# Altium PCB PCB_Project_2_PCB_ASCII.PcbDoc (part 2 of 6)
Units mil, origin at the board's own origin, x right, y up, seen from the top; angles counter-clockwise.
Board outline 3900 x 7800 mil, 6 copper layers (Top Layer, GND 1, Signal, Power, GND 2, Bottom Layer), stack 62.1 mil thick; 636 components, 334 nets, 1830 pads, 1401 vias.
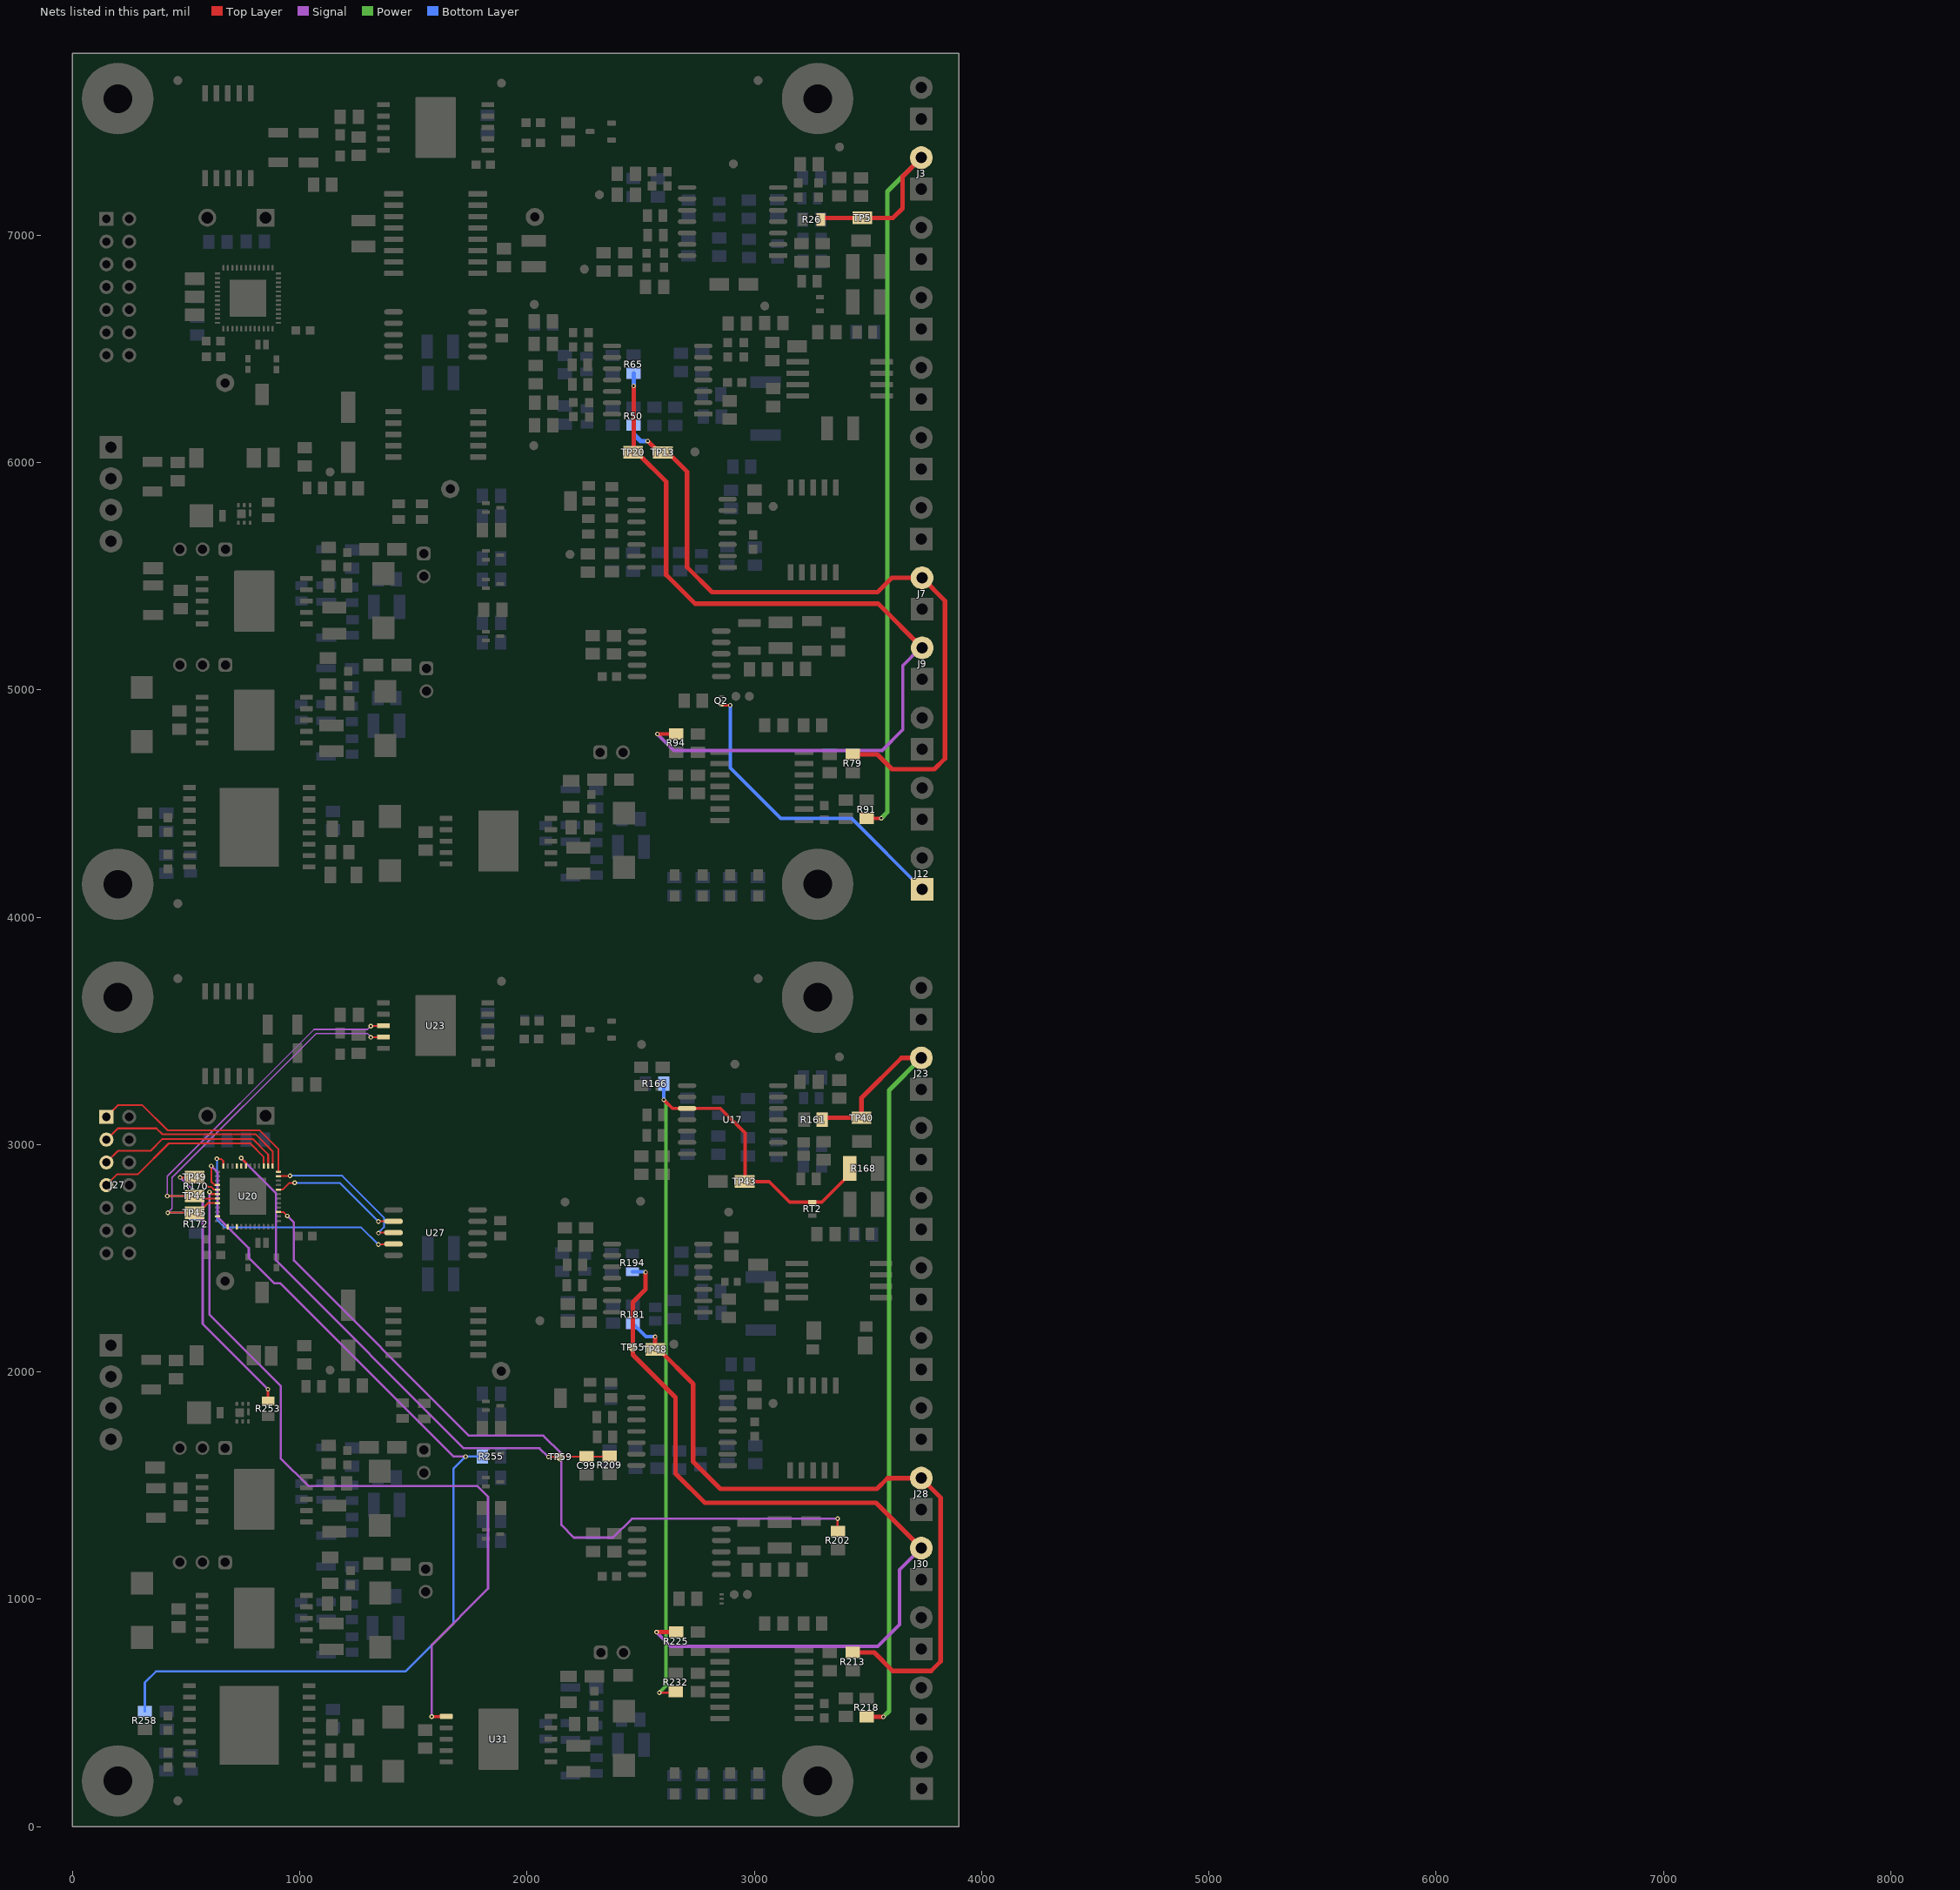
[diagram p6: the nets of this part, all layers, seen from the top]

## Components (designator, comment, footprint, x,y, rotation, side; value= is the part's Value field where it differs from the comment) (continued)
R212 "RT0805BRD0735K7L" 0805_HV 2574.22,1616.61 r90 bottom
R213 "ERJ-6ENF1372V" 0805_HV 3433,726 r90 top
R214 "ERJ-6ENF1502V" 0805_HV 3086,894 r180 top
R215 "CRCW080510K0FKEA" 0805_HV 3257.25,894 r180 top
R216 "ERJ-6ENF1001V" 0805_HV 3332.42,726 r270 top
R217 "ERJ-6GEYJ102V" 0805_HV 2894.38,184.79 r90 bottom
R218 "ERJ-6ENF1372V" 0805_HV 3495,524 r270 top
R219 "RR1220P-202-D" 0805_HV 3403,524.5 r90 top
R220 "ERJ-6GEYJ103V" 0805_HV 2938,2033 r180 bottom
R221 "ERJ-6GEYJ102V" 0805_HV 2879.81,1901.84 r270 bottom
R222 "RT0805BRD07626RL" 0805_HV 3000.72,1901.54 r90 top
R223 "ERJ-6GEYJ102V" 0805_HV 2773.24,184.79 r90 bottom
R224 "ERJ-6GEYJ104V" 0805_HV 3000.72,1901 r270 bottom
R225 "CRCW080510K7FKEA" 0805_HV 2656.04,815.81 r90 top
R226 "CRCW080514K7FKEA" 0805_HV 2751.35,816 r270 top
R227 "5106" 5106 2369.76,1919.81 r90 top
R228 "5106" 5106 2370,1909 r270 bottom
R229 "5106" 5106 2277.42,1920.55 r270 top
R230 "ERJ-6GEYJ102V" 0805_HV 2648.42,184.79 r90 bottom
R231 "5106" 5106 1882.44,2632 r270 top
R232 "ERJ-6ENF1102V" 0805_HV 2655.24,634.57 r270 top
R233 "CRCW080510K0FKEA" 0805_HV 2751.35,634.57 r90 top
R234 "5106" 5106 1453.1,1829.23 r90 top
R235 "5106" 5106 1549.06,1827.25 r90 top
R236 "RG2012P-102-B-T5" 0805_HV 1236.26,1939.42 r0 top
R237 "5106" 5106 1063.03,1937.05 r180 top
R238 "RC0603FR-0749R9L" 0603 1224.13,1094.55 r270 top
R239 "RC1206FR-073K9L" 1206 1134.69,1127.56 r90 top
R240 "5106" 5106 1007.16,950.73 r90 bottom
R241 "5106" 5106 1230.01,943.96 r90 bottom
R242 "5106" 5106 1231.36,801.72 r270 bottom
R243 "RG2012P-222-B-T5" 0805_HV 1230.01,1102.46 r90 bottom
R244 "RC0603FR-0749R9L" 0603 1209.85,1622.27 r270 top
R245 "ERJ-6GEYJ304V" 0805_HV 1844.04,1813 r180 bottom
R246 "RG2012P-4021-B-T5" 0805_HV 1127.05,1636.51 r90 top
R247 "ERJ-6ENF5761V" 0805_HV 1176.98,4286.01 r180 top
R248 "5106" 5106 1007.88,1473.9 r90 bottom
R249 "5106" 5106 1230.72,1467.12 r90 bottom
R250 "ERJ-6GEYJ302V" 0805_HV 1844.59,1752.65 r0 top
R251 "5106" 5106 1230.72,1327.76 r270 bottom
R252 "RT0805BRD076K42L" 0805_HV 320.45,4417.45 r270 top
R253 "5106" 5106 861.69,1838 r90 top
R254 "RT0805BRD07459RL" 0805_HV 1230.72,1625.62 r90 bottom
R255 "ERJ-6GEYJ203V" 0805_HV 1844.04,1627.66 r0 bottom
R256 "RN73C2A100KBTD" RN73_2A 524,283 r270 bottom
R257 "ERJ-6GEYJ203V" 0805_HV 1844.04,1535 r0 bottom
R258 "ERJ-6GEYJ203V" 0805_HV 319.12,466.75 r270 bottom
R259 "ERJ-6GEYJ302V" 0805_HV 1843.72,1401.59 r0 top
R260 "ERJ-6GEYJ304V" 0805_HV 1844.04,1257.77 r0 bottom
R261 "RC0603FR-0749R9L" 0603 2296.59,564.23 r270 top
R262 "RC1206FR-073K9L" 1206 2183.74,604.04 r90 top
R263 "5106" 5106 2082.07,418.49 r90 bottom
R264 "5106" 5106 2304.91,411.72 r90 bottom
R265 "5106" 5106 2306.27,269.47 r270 bottom
R266 "RG2012P-222-B-T5" 0805_HV 2304.91,570.22 r90 bottom
R267 "ERJ-6GEYJ203V" 0805_HV 416,467 r270 bottom
R268 "CRCW080510K7FKEA" 0805_HV 413,285 r90 bottom
R269 "ERJ-6ENF5761V" 0805_HV 1176.72,335.56 r180 top
R270 "RT0805BRD076K42L" 0805_HV 320.19,466.99 r270 top
RT1 "ERT-J1VG103HA" 0603S 3289,6697 r90 top
RT2 "ERT-J1VG103HA" 0603S 3255.41,2717 r90 top
S1 "SW_SPST-single" SW_PTS635SL50 721.77,7076.46 r180 top
S2 "SW_SPST-single" SW_PTS635SL50 721.77,3126.46 r180 top
TP1 "S2751-46R" Harwin_S2751-46R#1 3470.28,6975.71 r0 top
TP2 "TP_SM_1MM" TP_SM_1MM 2908.22,7313 r0 top
TP3 "TP_SM_1MM" TP_SM_1MM 2739.13,6046.56 r0 top
TP4 "5001" Keystone5001 2034.89,7079.54 r0 top
TP5 "S2751-46R" Harwin_S2751-46R#1 3475.45,7075.45 r180 top
TP6 "TP_SM_1MM" TP_SM_1MM 3375.38,7387.4 r0 top
TP7 "TP_SM_1MM" TP_SM_1MM 2318.74,7177.29 r0 top
TP8 "S2751-46R" Harwin_S2751-46R#1 2973.9,6784.12 r0 top
TP9 "S2751-46R" Harwin_S2751-46R#2 548.45,6728.74 r0 top
TP10 "S2751-46R" Harwin_S2751-46R#3 549.81,6649.83 r0 top
TP11 "TP_SM_1MM" TP_SM_1MM 2252.76,6850.1 r0 top
TP12 "S2751-46R" Harwin_S2751-46R#1 2846.04,6782.86 r0 top
TP13 "S2751-46R" Harwin_S2751-46R#1 2598.1,6043.86 r0 top
TP14 "S2751-46R" Harwin_S2751-46R#4 547.1,6800.88 r0 top
TP15 "TP_SM_1MM" TP_SM_1MM 2030.13,6073.66 r0 top
TP16 "5001" Keystone5001 672.38,6349.78 r270 top
TP17 "S2751-46R" Harwin_S2751-46R#1 3188.69,6510.68 r0 top
TP18 "TP_SM_1MM" TP_SM_1MM 3046.16,6688 r0 top
TP19 "TP_SM_1MM" TP_SM_1MM 1888,7668 r0 top
TP20 "S2751-46R" Harwin_S2751-46R#1 2466.41,6044.65 r180 top
TP21 "TP_SM_1MM" TP_SM_1MM 2032.55,6695.01 r0 top
TP22 "TP_SM_1MM" TP_SM_1MM 2978.54,4971.35 r0 top
TP23 "TP_SM_1MM" TP_SM_1MM 2919.34,4971.35 r0 top
TP24 "TP_SM_1MM" TP_SM_1MM 2189.25,5595.74 r0 top
TP25 "TP_SM_1MM" TP_SM_1MM 3083.54,5806.46 r0 top
TP26 "S2751-46R" Harwin_S2751-46R#1 2191.86,5831 r90 top
TP27 "TP_SM_1MM" TP_SM_1MM 1134,5958 r90 top
TP28 "S2751-46R" Harwin_S2751-46R#1 1448,5109.78 r180 top
TP29 "S2751-46R" Harwin_S2751-46R#1 1323.48,5109.78 r180 top
TP30 "5001" Keystone5001 1662.54,5883.3 r90 top
TP31 "S2751-46R" Harwin_S2751-46R#1 1427.94,5617.78 r0 top
TP32 "S2751-46R" Harwin_S2751-46R#1 885.6,6021.75 r270 top
TP33 "S2751-46R" Harwin_S2751-46R#1 355.58,5534.94 r180 top
TP34 "S2751-46R" Harwin_S2751-46R#1 1305.55,5617.78 r180 top
TP35 "S2751-46R" Harwin_S2751-46R#1 2426.77,4605 r180 top
TP36 "S2751-46R" Harwin_S2751-46R#1 2308,4605 r180 top
TP37 "S2751-46R" Harwin_S2751-46R#1 3474,3013 r0 top
TP38 "TP_SM_1MM" TP_SM_1MM 2915,3353.48 r0 top
TP39 "TP_SM_1MM" TP_SM_1MM 2646.5,2122.08 r0 top
TP40 "S2751-46R" Harwin_S2751-46R#1 3472,3118 r0 top
TP41 "TP_SM_1MM" TP_SM_1MM 3374.56,3385.55 r0 top
TP42 "TP_SM_1MM" TP_SM_1MM 2504.2,3440.36 r0 top
TP43 "S2751-46R" Harwin_S2751-46R#1 2957.81,2837.65 r0 top
TP44 "S2751-46R" Harwin_S2751-46R#1 538.23,2773.62 r0 top
TP45 "S2751-46R" Harwin_S2751-46R#1 538.75,2699.83 r0 top
TP46 "TP_SM_1MM" TP_SM_1MM 2499.82,2750.47 r0 top
TP47 "S2751-46R" Harwin_S2751-46R#1 2839.74,2837.56 r180 top
TP48 "S2751-46R" Harwin_S2751-46R#1 2564,2099.1 r0 top
TP49 "S2751-46R" Harwin_S2751-46R#1 538.75,2856.79 r0 top
TP50 "TP_SM_1MM" TP_SM_1MM 2057,2225 r0 top
TP51 "5001" Keystone5001 672.38,2399.78 r270 top
TP52 "TP_SM_1MM" TP_SM_1MM 2887.51,2703 r0 top
TP53 "S2751-46R" Harwin_S2751-46R#1 3017,2471.4 r180 top
TP54 "TP_SM_1MM" TP_SM_1MM 1888,3718 r0 top
TP55 "TP_SM_1MM" TP_SM_1MM 2466.15,2108.67 r0 top
TP56 "TP_SM_1MM" TP_SM_1MM 2167.62,2747 r0 top
TP57 "TP_SM_1MM" TP_SM_1MM 2969.81,1021.56 r180 top
TP58 "TP_SM_1MM" TP_SM_1MM 2912,1021 r0 top
TP59 "TP_SM_1MM" TP_SM_1MM 2146.9,1626.68 r0 top
TP60 "TP_SM_1MM" TP_SM_1MM 3083.06,1861.54 r0 top
TP61 "S2751-46R" Harwin_S2751-46R#1 2147.16,1884.31 r90 top
TP62 "TP_SM_1MM" TP_SM_1MM 1134,2008 r90 top
TP63 "S2751-46R" Harwin_S2751-46R#1 1445.35,1154.34 r180 top
TP64 "5001" Keystone5001 1886.55,2003.98 r90 top
TP65 "S2751-46R" Harwin_S2751-46R#1 1323.48,1158 r180 top
TP66 "S2751-46R" Harwin_S2751-46R#1 1427.94,1667.78 r0 top
TP67 "S2751-46R" Harwin_S2751-46R#1 874.32,2071.01 r270 top
TP68 "S2751-46R" Harwin_S2751-46R#1 364.46,1579.62 r0 top
TP69 "S2751-46R" Harwin_S2751-46R#1 1305.55,1667.78 r180 top
TP70 "S2751-46R" Harwin_S2751-46R#1 2423.27,666.23 r180 top
TP71 "S2751-46R" Harwin_S2751-46R#1 2296.59,661.13 r180 top
U1 "LMP7704-SP" 0-IPC_C 2905.02,7059.19 r180 top locked
U2 "LMP7704-SP" 0-IPC_C 2574.91,6362.45 r180 top locked
U3 "LMP7704-SP" 0-IPC_C 2682.19,5688.47 r180 top locked
U4 "CON-ADC-ADC108S052CIMT" NAC0016A_N 1598.66,7006.57 r180 top locked
U5 "LM4050WG2.5-MPR" NAC0010A-IPC_C 684.39,7437.14 r270 top locked
U6 "MSP430FR5969IRGZ" RGZ0048B 773.11,6722.32 r180 top locked
U7 "INA901HKX/EM" HKX0008A_Custom_A 3376.02,6367.56 r180 top locked
U8 "TMP461HKU/EM" HKU0010_CUSTOM_A 1598.28,7473.17 r180 top locked
U9 "LM158AWGRQMLV" NAC0010A_N 2669.67,5158.53 r180 top locked
U10 "LM139AWGRLQMLV" NAC0014A_N 3033.96,4575.46 r180 top locked
U11 "LM4050WG2.5-MPR" NAC0010A-IPC_C 3259.42,5703.13 r90 top locked
U12 "DAC121S101WGMPR" NAC0010A_N 1598.03,6562.51 r180 top locked
U13 "TPS7A4501HKU/EM" HKU0010_CUSTOM_A 800.07,4866.92 r0 top locked
U14 "LM4050WG5.0-MPR" NAC0010A-IPC_C 1598.6,6123.66 r180 top locked
U15 "TPS7A4501HKU/EM" HKU0010_CUSTOM_A 800.79,5390.09 r0 top locked
U16 "TPS7A4501HKU/EM" HKU0010_CUSTOM_A 1874.92,4334.68 r0 top locked
U17 "LMP7704-SP" 0-IPC_C 2905.02,3109.19 r180 top locked
U18 "LMP7704-SP" 0-IPC_C 2575.3,2412.5 r180 top locked
U19 "LM4050WG2.5-MPR" NAC0010A-IPC_C 684.39,3487.14 r270 top locked
U20 "MSP430FR5969IRGZ" RGZ0048B 773.11,2772.32 r180 top locked
U21 "LMP7704-SP" 0-IPC_C 2682.19,1738.47 r180 top locked
U22 "INA901HKX/EM" HKX0008A_Custom_A 3372.47,2401.63 r180 top locked
U23 "TMP461HKU/EM" HKU0010_CUSTOM_A 1598.28,3523.17 r180 top locked
U24 "LM158AWGRQMLV" NAC0010A_N 2669.67,1208.53 r180 top locked
U25 "LM139AWGRLQMLV" NAC0014A_N 3033.96,625.45 r180 top locked
U26 "LM4050WG2.5-MPR" NAC0010A-IPC_C 3258.43,1753.13 r90 top locked
U27 "DAC121S101WGMPR" NAC0010A_N 1598.03,2612.52 r180 top locked
U28 "TPS7A4501HKU/EM" HKU0010_CUSTOM_A 800.07,916.93 r0 top locked
U29 "LM4050WG5.0-MPR" NAC0010A-IPC_C 1598.6,2173.66 r180 top locked
U30 "TPS7A4501HKU/EM" HKU0010_CUSTOM_A 800.79,1440.09 r0 top locked
U31 "TPS7A4501HKU/EM" HKU0010_CUSTOM_A 1874.98,384.68 r0 top locked
U32 "TPS7H2201HKR/EM" HKR0016A_Custom_A 778.62,4395.75 r0 top locked
U33 "TPS7H2201HKR/EM" HKR0016A_Custom_A 778.37,445.29 r0 top locked
Y1 "XTAL_3P_12_G3" XTAL_MS3V-T1R 834.5,6408.8 r270 top
Y2 "XTAL_3P_12_G3" XTAL_MS3V-T1R 834.5,2458.8 r270 top
ZZ1 "This Assembly Note is for PCB labels only" AssemblyNoteLabel 4989,6984 r0 top
ZZ2 "These assemblies are ESD sensitive, ESD precautions shall be observed." AssemblyNote 4980,6860 r0 top
ZZ3 "These assemblies must be clean and free from flux and all contaminants. Use of no clean flux is not acceptable." AssemblyNote 4985,6774 r0 top
ZZ4 "These assemblies must comply with workmanship standards IPC-A-610 Class 2, unless otherwise specified." AssemblyNote 4985,6678 r0 top

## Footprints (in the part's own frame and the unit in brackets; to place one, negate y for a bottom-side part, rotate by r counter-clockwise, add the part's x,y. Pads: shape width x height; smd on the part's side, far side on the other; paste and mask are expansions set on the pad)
0-IPC_C [mil]
  rrect19% 80.92x20.66 smd paste+0 mask+0: 1(-200.54,150)
  rrect100% 80.92x20.66 smd paste+0 mask+0: 2(-200.54,100) 3(-200.54,50) 4(-200.54,0) 5(-200.54,-50) 6(-200.54,-100) 7(-200.54,-150) 8(200.54,-150) 9(200.54,-100) 10(200.54,-50) 11(200.54,0) 12(200.54,50) 13(200.54,100) 14(200.54,150)
  silkscreen extent -230,-192 140,192
3M_x2514-60xx [mil] "3M"
  rect 62x62 hole 37 paste+2: 1(-300,-50)
  round 62 hole 37: 2(-300,50) 3(-200,-50) 4(-200,50) 5(-100,-50) 6(-100,50) 7(0,-50) 8(0,50) 9(100,-50) 10(100,50) 11(200,-50) 12(200,50) 13(300,-50) 14(300,50)
  silkscreen extent -494,-163 494,177
0402 [mm] "0402 from SM-752 data"
  rect 0.8x0.6 smd: 1(-0.6,0) 2(0.6,0)
  silkscreen extent -1.22,-0.52 1.22,0.52
0603 [mm] "0603 from SM-752 data"
  rect 1x0.95 smd: 1(-0.8,0) 2(0.8,0)
  silkscreen extent -1.52,-0.69 1.52,0.69
0603L [mm] "0603 from SM-752 data"
  rect 0.8x0.85 smd: 1(-0.7,0) 2(0.7,0)
  silkscreen extent -0.07,-0.33 0.07,0.33
0603S [mil]
  rect 20x35 smd: 1(-30,0) 2(30,0)
0805_HV [mil] "0805 with 30mil clearance between pads"
  rect 50x63 smd: 1(-40,0) 2(40,0)
  silkscreen extent -74,-40 74,40
0805L [mm] "0805 from SM-752 data"
  rect 1.1x1.4 smd: 1(-0.75,0) 2(0.75,0)
1206 [mm] "1206 from SM-752 data"
  rect 1.3x1.85 smd: 1(-1.45,0) 2(1.45,0)
  silkscreen extent -2.4,-1.21 2.4,1.21
1210 [mm] "1210 from SM-752 data"
  rect 1.3x2.7 smd: 1(-1.45,0) 2(1.45,0)
  silkscreen extent -2.32,-1.57 2.32,1.57
1210_200 [mm] "1210"
  rect 1.3x2.7 smd: 1(-1.45,0) 2(1.45,0)
  silkscreen extent -2.32,-1.57 2.32,1.57
1210_220 [mm] "1210"
  rect 1.3x2.7 smd: 1(-1.45,0) 2(1.45,0)
  silkscreen extent -2.32,-1.57 2.32,1.57
1210_280 [mm] "SMD, 2-Leads, Body 3.6x2.8mm, Height 2.8mm"
  rect 1.1x2.2 smd: 1(-1.65,0) 2(1.65,0)
  silkscreen extent -0.84,-1.4 0.84,1.4
1210M [mm] "1210 from SM-752 data"
  rect 1.5x2.8 smd: 1(-1.55,0) 2(1.55,0)
  silkscreen extent -2.75,-1.85 2.75,1.85
2512 [mm] "Chip Resistor, Body 6.3x3.2mm, IPC Medium Density"
  rect 1.3x3.4 smd: 1(-2.95,0) 2(2.95,0)
  silkscreen extent -1.9,-1.6 1.9,1.6
5106 [mm] "Keystone"
  rect 0.99x1.4 smd: 1(-0.85,0) 2(0.88,0)
  silkscreen extent -1.63,-0.98 1.65,0.98
7343-31 [mm] "Medium Density based on Kemet T495 dimensions"
  rect 2.55x2.45 smd: 1(-3.025,0) 2(3.025,0)
  silkscreen extent -4.56,-2.3 3.8,2.3
7343-43 [mm] "Medium density IPC based on Kemet T495 series"
  rect 2.55x2.45 smd: 1(-3.025,0) 2(3.025,0)
  silkscreen extent -4.56,-2.3 3.8,2.3
AssemblyNote [mil] "Assembly Note"
AssemblyNoteLabel [mil] "Assembly Note for PCB Labels"
Bumpon_SJ5003Transparent [mil] "3M Hemispherical Bumpon transparent"
  round 1 on Mech4: 0(0,0)
  silkscreen extent -228,-228 228,228
CE_Mark_5mm [mil] "Minimum text height for CE Mark"
CSM2512_T3 [mm] "SMD, 4-Leads, Body 6.35x3.175mm"
  rect 1.65x2.01 smd: 1(-2.855,0.835) 2(2.855,-0.835)
  rect 1.39x1.14 smd: 3(-2.985,-1.27) 4(2.985,1.27)
  silkscreen extent -2,-1.59 2,1.8
DO-220AA [mil] "Vishay recommended land pattern 12-Mar-12"
  rect 105.12x100 smd: 1(-46.28,0)
  rect 30x50 smd: 2(46.28,0)
  silkscreen extent 19,-43 58,43
DQK0006C [mm] "WSON"
  rrect12% 0.9x0.86 on Top Paste: 0(0,0.325)
  rrect34% 0.7x0.29 on Top Paste: 0(0.095,-0.65)
  rrect33% 0.45x0.3 smd: 1(-0.975,0.65) 2(-0.975,0) 3(-0.975,-0.65) 4(0.975,-0.65) 5(0.975,0) 6(0.975,0.65)
  rrect33% 0.75x0.3 smd paste-0.15: 7(0.095,-0.65)
  rrect11% 1x0.95 smd paste-0.5: 8(0,0.325)
  silkscreen extent -1.15,-1.15 1.15,1.15
FCC_disclaimer [mil]
Fiducial10-20 [mm]
  round 1 smd mask+0: 1(0,0)
  Top Layer keep-out circle w1.178: c0,0 r0.5
FP-7447773151_SMT_IND_7MM4_7MM3-MFG [mm]
  rrect6% 1.6x2.2 smd paste+0 mask+0: 1(-3.2,0) 2(3.2,0)
  silkscreen extent -4.63,-3.8 3.85,3.8
FP-885012209041_1210-MFG [mm]
  rrect11% 0.9x2.5 smd paste+0 mask+0: 1(-1.55,0) 2(1.55,0)
  silkscreen extent -0.72,-1.35 0.72,1.35
Harwin_S2751-46R#1 [mm] "Test Point, SMT"
  rect 2.2x1.4 smd: 1(0,0)
Harwin_S2751-46R#2 [mm] "Test Point, SMT"
  rect 2.2x1.4 smd: 1(-0.246,0)
Harwin_S2751-46R#3 [mm] "Test Point, SMT"
  rect 2.2x1.4 smd: 1(-0.281,0)
Harwin_S2751-46R#4 [mm] "Test Point, SMT"
  rect 2.2x1.4 smd: 1(-0.212,0.172)
HKR0016A_Custom_A [mil] "16-Leads, Body 11.3x9.9mm, Pitch 1.27mm, Thermal Pad 9x6.78mm"
  rrect25% 56x22 smd: 1(-263.5,175) 2(-263.5,125) 3(-263.5,75) 4(-263.5,25) 5(-263.5,-25) 6(-263.5,-75) 7(-263.5,-125) 8(-263.5,-175) 9(263.5,-175) 10(263.5,-125) 11(263.5,-75) 12(263.5,-25) 13(263.5,25) 14(263.5,75) 15(263.5,125) 16(263.5,175)
  rect 259.45x346.46 smd: 17(0,0)
  silkscreen extent -273,-222 194,221
HKU0010_CUSTOM_A [mm] "HKU custom footprint"
  rrect18% 1.42x0.55 smd: 1(-5.84,2.54) 2(-5.84,1.27) 3(-5.84,0) 4(-5.84,-1.27) 5(-5.84,-2.54) 6(5.84,-2.54) 7(5.84,-1.27) 8(5.84,0) 9(5.84,1.27) 10(5.84,2.54)
  rrect11% 0.95x0.95 on Top Paste: 11(-1.725,1.725) 11(-1.725,2.875) 11(-1.725,-0.575) 11(-1.725,0.575) 11(-1.725,-1.725) 11(-1.725,-2.875) 11(-0.575,1.725) 11(-0.575,2.875) 11(-0.575,0.575) 11(-0.575,-0.575) 11(-0.575,-1.725) 11(-0.575,-2.875) 11(0.575,1.725) 11(0.575,0.575) 11(0.575,2.875) 11(0.575,-0.575) 11(0.575,-1.725) 11(0.575,-2.875) 11(1.725,2.875) 11(1.725,-0.575) 11(1.725,-2.875) 11(1.725,1.725) 11(1.725,0.575) 11(1.725,-1.725)
  rrect4% 4.5x6.82 smd paste-3 mask+0: 11(0,0)
  silkscreen extent -3.56,-3.68 3.56,3.68
HKX0008A_Custom_A [mm] "CFP, 8-Leads, Body 6.475x6.485mm, Pitch 1.27mm"
  rrect17% 2.5x0.6 smd: 1(-4.7,1.905) 2(-4.7,0.635) 3(-4.7,-0.635) 4(-4.7,-1.905) 5(4.7,-1.905) 6(4.7,-0.635) 7(4.7,0.635) 8(4.7,1.905)
  silkscreen extent -5.5,-3.36 3.37,3.36
Keystone5001 [mil] "For Keystone 500x miniature loop terminals"
  round 80 hole 40: 1(0,0)
  silkscreen extent -52,-52 52,52
Keystone_1902C [mil] "Hex Standoff, 4-40 threaded, nylon"
  round 1 on Mech4: 0(0,0)
Label_650x200 [mil] "Thermal Transfer Label"
  round 1 on Mech13: 0(0,0)
  silkscreen extent -325,-100 325,100
Lumex_SML-LXF0805SRC_RED [mm] "SMD, 2-Leads, Body 2x1.25mm"
  rrect9% 1.25x1.1 smd: 1(-1.175,0) 2(1.175,0)
NAC0010A-IPC_C [mm]
  rrect16% 1.79x0.63 smd paste+0 mask+0: 1(-4.74,2.54) 2(-4.74,1.27) 3(-4.74,0) 4(-4.74,-1.27) 5(-4.74,-2.54) 6(4.74,-2.54) 7(4.74,-1.27) 8(4.74,0) 9(4.74,1.27) 10(4.74,2.54)
  silkscreen extent -6.48,-3.43 3.31,3.43
NAC0010A_N [mm] "SOP, 10-Leads, Body 6.9x6.6mm (max), Pitch 1.27mm, IPC Normal Density"
  oval 2.1x0.6 smd: 1(-4.7,2.54) 2(-4.7,1.27) 3(-4.7,0) 4(-4.7,-1.27) 5(-4.7,-2.54) 6(4.7,-2.54) 7(4.7,-1.27) 8(4.7,0) 9(4.7,1.27) 10(4.7,2.54)
  silkscreen extent -3.44,-3.43 3.06,3.42
NAC0014A_N [mm] "CFP-14"
  rrect17% 2.1x0.6 smd: 1(-4.7,3.81) 2(-4.7,2.54) 3(-4.7,1.27) 4(-4.7,0) 5(-4.7,-1.27) 6(-4.7,-2.54) 7(-4.7,-3.81) 8(4.7,-3.81) 9(4.7,-2.54) 10(4.7,-1.27) 11(4.7,0) 12(4.7,1.27) 13(4.7,2.54) 14(4.7,3.81)
  silkscreen extent -4.83,-4.97 3.25,4.97
NAC0016A_N [mm] "CFP, 16-Leads, Body 9.91x6.85mm, Pitch 1.27mm, IPC Medium Density"
  rrect17% 2.1x0.6 smd: 1(-4.7,4.445) 2(-4.7,3.175) 3(-4.7,1.905) 4(-4.7,0.635) 5(-4.7,-0.635) 6(-4.7,-1.905) 7(-4.7,-3.175) 8(-4.7,-4.445) 9(4.7,-4.445) 10(4.7,-3.175) 11(4.7,-1.905) 12(4.7,-0.635) 13(4.7,0.635) 14(4.7,1.905) 15(4.7,3.175) 16(4.7,4.445)
  silkscreen extent -5.25,-4.98 3,4.97
"NY PMS 440 0025 PH" [mm] "4-40 nylon screw and mounting hole"
  round 8 hole 3.2: 1(0,0)
RGZ0048B [mm] "QFN, 48-Leads, Body 7x7mm, Pitch 0.5mm, Thermal Pad 5.15x5.15mm, TI Recommended"
  rrect42% 0.6x0.24 smd: 1(-3.4,2.75) 2(-3.4,2.25) 3(-3.4,1.75) 4(-3.4,1.25) 5(-3.4,0.75) 6(-3.4,0.25) 7(-3.4,-0.25) 8(-3.4,-0.75) 9(-3.4,-1.25) 10(-3.4,-1.75) 11(-3.4,-2.25) 12(-3.4,-2.75) 25(3.4,-2.75) 26(3.4,-2.25) 27(3.4,-1.75) 28(3.4,-1.25) 29(3.4,-0.75) 30(3.4,-0.25) 31(3.4,0.25) 32(3.4,0.75) 33(3.4,1.25) 34(3.4,1.75) 35(3.4,2.25) 36(3.4,2.75)
  rrect42% 0.24x0.6 smd: 13(-2.75,-3.4) 14(-2.25,-3.4) 15(-1.75,-3.4) 16(-1.25,-3.4) 17(-0.75,-3.4) 18(-0.25,-3.4) 19(0.25,-3.4) 20(0.75,-3.4) 21(1.25,-3.4) 22(1.75,-3.4) 23(2.25,-3.4) 24(2.75,-3.4) 37(2.75,3.4) 38(2.25,3.4) 39(1.75,3.4) 40(1.25,3.4) 41(0.75,3.4) 42(0.25,3.4) 43(-0.25,3.4) 44(-0.75,3.4) 45(-1.25,3.4) 46(-1.75,3.4) 47(-2.25,3.4) 48(-2.75,3.4)
  rrect9% 1.17x1.17 on Top Paste: 49(-1.37,1.37) 49(-1.37,0) 49(-1.37,-1.37) 49(0,-1.37) 49(0,1.37) 49(0,0) 49(1.37,1.37) 49(1.37,0) 49(1.37,-1.37)
  rrect2% 4.1x4.1 smd paste-2.575: 49(0,0)
  silkscreen extent -3.72,-3.72 3.73,3.73
RN73_2A [mm] "TE Connectivity 0805"
  rect 1x1.45 smd: 1(-1,0) 2(1,0)
  silkscreen extent -1.85,-1 1.85,1
Samtec_TSW-102-07-T-S [mm] "Header, 2.54 mm, 2x1, Tin, TH"
  rrect50% 1.55x1.55 hole 1.02: 1(-1.27,0)
  round 1.55 hole 1.02: 2(1.27,0)
Samtec_TSW-103-07-T-S [mm] "Header, 2.54 mm, 3x1, TH"
  rrect50% 1.55x1.55 hole 1.02: 1(-2.54,0)
  round 1.55 hole 1.02: 2(0,0) 3(2.54,0)
SOT-23 [mm] "SOT23, 3-Leads, Body 2.9x1.3mm, Pitch 0.95mm, Lead Span 2.5mm, IPC Medium Density"
  rrect50% 1x0.6 smd: 1(-1.2,0.95) 2(-1.2,-0.95) 3(1.2,0)
  silkscreen extent 0.2,-1.5 0.7,1.5
SOT-523 [mm] "From Diodes Inc datasheet component parameters"
  rect 0.9x0.4 smd: 1(-0.8,0.5) 2(-0.8,-0.5) 3(0.8,0)
  silkscreen extent 0.02,-0.85 0.42,0.85
ST_LCC-2D [mm] "ST Microelectronics"
  rect 0.9x2.2 smd: 1(-2,0) 2(2,0)
  silkscreen extent -1.25,-1.25 1.25,1.25
SW_PTS635SL50 [mm] "C&K"
  rect 2x2 hole 1.3: 1(-3.25,0)
  round 2 hole 1.3: 2(3.25,0)
  silkscreen extent -3.22,-1.95 3.22,1.95
TERM_BLK_ED555-2DS [mil]
  rrect4% 100x100 hole 50: 1(0,0)
  round 100 hole 50: 2(138,0)
  silkscreen extent -77,-159 215,113
TERM_BLK_ED555-4DS [mm]
  rect 2.54x2.54 hole 1.27: 1(0,0)
  round 2.54 hole 1.27: 2(3.5,0) 3(7,0) 4(10.5,0)
  silkscreen extent -1.75,-3.83 12.25,2.67
TI_Stacked_Overlay_Small [mil]
TP_SM_1MM [mm] "1mm Test Point, SMT"
  round 1 smd paste-0.5: 1(0,0)
WCAP-ASLI_630x550 [mm] "SMD, 2-Leads, Dia 6.3mm"
  rrect6% 3.5x1.6 smd: 1(-2.8,0) 2(2.8,0)
  silkscreen extent -3.3,-3.3 3.3,3.3
WEEE_Minimum [mil] "WEEElie bin"
  silkscreen extent 22,-71 54,74
XTAL_MS3V-T1R [mm] "Micro Crystal Switzerland recommended land pattern"
  rect 1.1x0.6 smd: 1(-2.775,0.45) 2(-2.775,-0.45)
  rect 2.4x1.5 smd: 3(2.775,0)
  silkscreen extent -1.9,-0.74 1.2,0.74
YJK0003A [mm] "SMD, 3-Leads, Body 1.49x0.73mm"
  rrect50% 0.2x0.39 on Top Paste: 1(-0.525,0) 2(0,0) 3(0.525,0)
  rrect80% 0.25x0.49 smd paste-0.15 mask+0: 1(-0.5,0) 2(0,0) 3(0.5,0)
  silkscreen extent -0.9,-0.5 0.9,0.5

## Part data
C1 C70: library part CMP-0008095-2, "CAP, CERM, 110 pF, 100 V, +/- 5%, C0G/NP0, 0805"
C2 C7 C10 C15 C19 C22 C27 C32: library part CMP-0008088-2, "CAP, CERM, 620 pF, 50 V, +/- 5%, C0G/NP0, 0805"
C3 C4 C34 C35 C72 C82 C94 C98: library part CMP-0006862-5, "CAP, CERM, 0.1 uF, 10 V, +/- 10%, X7R, 0603"
C5 C24: library part CMP-0007631-2, "CAP, CERM, 0.1 uF, 50 V, +/- 5%, X7R, 0805"
C6 C8 C38 C97: library part CMP-0009251-2, "CAP, CERM, 1 uF, 50 V, +/- 10%, X7R, 1210"
C9 C11 C16 C21 C25 C30: library part CMP-0007211-4, "CAP, CERM, 36 pF, 50 V, +/- 5%, C0G/NP0, 0603"
C12 C75: library part CMP-0009078-1, "CAP, CERM, 10 uF, 25 V, +/- 10%, X7R, 1210"
C13 C76: library part CMP-0009167-2, "CAP, CERM, 4.7 uF, 25 V, +/- 10%, X8R, AEC-Q200 Grade 0, 1210"
C14 C18 C33 C77 C80 C92: library part CMP-0006815-4, "CAP, CERM, 0.1 uF, 10 V, +/- 10%, X7R, 0603"
C17 C79: library part CMP-0007002-5, "CAP, CERM, 1 uF, 10 V, +/- 10%, X5R, 0603"
C20: library part CMP-0008061-2, "CAP, CERM, 1100 pF, 50 V, +/- 5%, C0G/NP0, 0805"
C23 C26 C85 C86: library part CMP-0064911-2, "CAP, CERM, 10 pF, 50 V,+/- 2.5%, C0G/NP0, AEC-Q200 Grade 1, 0402"
C28 C29: library part CMP-0008030-3, "CAP, CERM, 33 pF, 50 V, +/- 5%, C0G/NP0, 0805"
C31 C91: library part CMP-0081453-1, "CAP, CERM, 100 pF, 50 V,+/- 5%, C0G/NP0, 0805"
C36 C95: library part CMP-0089025-1, "0.1µF ±10% 50V Ceramic Capacitor X7R 1210 (3225 Metric)"
C37 C56 C58 C96 C118 C120: library part CMP-0009258-1, "CAP, CERM, 10 uF, 50 V, +/- 10%, X7R, AEC-Q200 Grade 1, 1210"
C39 C78 C81 C84 C88 C93 C99: library part CMP-0008123-1, "CAP, CERM, 510 pF, 100 V, +/- 5%, C0G/NP0, 0805"
C40 C100: library part CMP-0009270-2, "CAP, CERM, 1000 pF, 500 V, +/- 10%, X7R, 1210"
C41 C47 C53 C65 C101 C106 C113 C125: library part CMP-0009075-1, "CAP, CERM, 0.1 uF, 50 V, +/- 10%, X7R, 1210"
C42 C102: library part CMP-0077988-1, "CAP, AL, 68 µF, 25 V, +/- 20%, SMD"
C43 C103: library part CMP-0008088-1, "CAP, CERM, 620 pF, 50 V, +/- 5%, C0G/NP0, 0805"
C44 C51 C63 C104 C111 C123: library part CMP-0008063-1, "CAP, CERM, 1200 pF, 50 V, +/- 5%, C0G/NP0, 0805"
C45 C54 C66 C107 C114 C126: library part CMP-0009190-2, "CAP, CERM, 10 uF, 25 V, +/- 10%, X7R, 1210"
C46 C52 C64 C105 C112 C124: library part CMP-0011763-1, "CAP, TA, 22 uF, 25 V, +/- 10%, 0.2 ohm, SMD"
C48 C55 C67 C108 C115 C127: library part CMP-0007565-2, "CAP, CERM, 0.1 uF, 25 V, +/- 5%, X7R, 0805"
C49 C68 C109 C128: library part CMP-0011813-2, "CAP, TA, 15 uF, 50 V, +/- 20%, 0.3 ohm, SMD"
C50 C57 C59 C60 C62 C69 C110 C116 C119 C121 C122 C129: library part CMP-0007634-1, "CAP, CERM, 1 uF, 50 V, +/- 10%, X7R, 0805"
C61 C133: library part CMP-0007739-1, "CAP, CERM, 0.12 uF, 50 V, +/- 10%, X7R, 0805"
C71 C73 C74: library part CMP-0008123-2, "CAP, CERM, 510 pF, 100 V, +/- 5%, C0G/NP0, 0805"
C83: library part CMP-0008061-1, "CAP, CERM, 1100 pF, 50 V, +/- 5%, C0G/NP0, 0805"
C87: library part CMP-0007631-1, "CAP, CERM, 0.1 uF, 50 V, +/- 5%, X7R, 0805"
C89 C90: library part CMP-0008030-2, "CAP, CERM, 33 pF, 50 V, +/- 5%, C0G/NP0, 0805"
C117 C132 C134 C137: library part CMP-0006856-6, "CAP, CERM, 0.1 uF, 25 V, +/- 5%, X7R, 0603"
C130 C131 C135 C136: library part CMP-0082630-1, "CAP, CERM, 2000 pF, 50 V,+/- 5%, C0G/NP0, 1206"
D1 D2 D3 D4 D5 D13 D14 D15 D16 D17: library part CMP-0084763-1, "LED, Red, SMD"
D6 D7 D9 D10 D11 D12 D18 D19 D21 D22 D23 D24: library part CMP-0076902-2, "Diode, Switching, 100 V, 0.3 A, LCC-2D"
D8 D20: library part CMP-0028608-2, "Diode, Schottky, 30 V, 1.5 A, DO-220AA"
FID1 FID2 FID3 FID4 FID5 FID6 FID7 FID8 FID9 FID10 FID11 FID12: library part CMP-0077181-1, "Fiducial mark.  There is nothing to buy or mount."
H1 H2 H3 H4 H5 H6 H7 H8: library part CMP-0003617-1, "Machine Screw, Round, #4-40 x 1/4, Nylon, Philips panhead"
H9 H10 H11 H12: library part CMP-0003620-1, "Bumpon, Hemisphere, 0.44 X 0.20, Clear"
H13 H14 H15 H16 H17 H18 H19 H20: library part CMP-0003610-1, "Standoff, Hex, 0.5\"L #4-40 Nylon"
J1 J2 J3 J4 J5 J7 J8 J9 J10 J12 J13 J14 J21 J22 J23 J25 J26 J28 J29 J30 J31 J32 J33 J34: library part CMP-0074913-1, "Terminal Block, 3.5mm Pitch, 2x1, TH"
J6 J27: library part CMP-0075023-2, "Header (shrouded), 100mil, 7x2, Gold, TH"
J15 J35: library part CMP-0074917-1, "Terminal Block, 3.5mm Pitch, 4x1, TH"
J16 J18 J20 J36 J38 J40: library part CMP-0075508-2, "Header, 2.54 mm, 2x1, Tin, TH"
J17 J19 J37 J39: library part CMP-0075530-2, "Header, 2.54 mm, 3x1, Tin, TH"
L1 L2: library part CMP-0089518-1, "150µH Shielded Wirewound Inductor 780mA 515mOhm Max Nonstandard"
LBL1: library part CMP-0003625-1, "Thermal Transfer Printable Labels, 0.650\" W x 0.200\" H - 10,000 per roll"
Logo1: library part CMP-0074844-1
Logo2: library part CMP-0074838-1, "Texas Instrument Corporate Signature"
Logo3: library part CMP-0074847-1, "FCC_disclaimer"
Logo4: library part CMP-0074769-1
Q1 Q10: library part CMP-0000419-2, "Transistor, NPN, 40 V, 0.2 A, SOT-23"
Q2 Q11: library part CMP-0000824-1, "MOSFET, N-CH, 60 V, 2.2 A, YJK0003A (PICOSTAR-3)"
Q3 Q14: library part CMP-0000248-1, "MOSFET, N-CH, 25 V, 5 A, DQK0006C (WSON-6)"
Q4 Q8 Q12 Q17: library part CMP-0000362-1, "Transistor, PNP, 60 V, 0.6 A, AEC-Q101, SOT-523"
Q6 Q9 Q15 Q18: library part CMP-0000405-2, "Transistor, NPN, 40 V, 0.2 A, SOT-523"
R1: library part CMP-0021817-3, "RES, 9.53 k, 1%, 0.125 W, AEC-Q200 Grade 0, 0805"
R2 R4 R5 R6 R7 R8 R20 R22 R27 R42 R51 R58 R67: library part CMP-0020833-2, "RES, 0, 1%, 0.5 W, 0805"
R3: library part CMP-0019913-1, "RES, 2.46 k, 0.1%, 0.125 W, 0805"
R9 R12 R73 R74 R99 R147 R150 R200 R201 R224: library part CMP-0020622-3, "RES, 100 k, 5%, 0.125 W, AEC-Q200 Grade 0, 0805"
R10: library part CMP-0020380-2, "RES, 89.8, 0.1%, 0.125 W, 0805"
R11 R148: library part CMP-0019917-2, "RES, 2.55 k, 0.1%, 0.125 W, 0805"
R13 R149: library part CMP-0019458-2, "RES, 10.2 k, 0.1%, 0.125 W, 0805"
R14 R15 R30: library part CMP-0019958-2, "RES, 32.4 k, 0.1%, 0.125 W, 0805"
R16 R19: library part CMP-0019695-2, "RES, 1.30 k, 0.1%, 0.125 W, 0805"
R17: library part CMP-0020317-2, "RES, 76.8, 0.1%, 0.125 W, 0805"
R18 R155: library part CMP-0078954-1, "RES, 0.082, 1%, 2 W, AEC-Q200 Grade 0, 2512"
R21 R29 R36 R47 R54 R59: library part CMP-0021520-3, "RES, 10.0 k, 1%, 0.125 W, AEC-Q200 Grade 0, 0805"
R23: library part CMP-0019606-2, "RES, 16.2 k, 0.1%, 0.125 W, 0805"
R24: library part CMP-0019747-2, "RES, 1.20 M, 0.1%, 0.125 W, 0805"
R25 R31 R38 R49 R55 R64: library part CMP-0025874-4, "RES, 0, 5%, 0.1 W, AEC-Q200 Grade 0, 0603"
R26 R125 R194 R256: library part CMP-0019070-2, "RES, 100 k, 0.1%, 0.1 W, 0805"
R28 R34 R43 R52 R57 R68: library part CMP-0020364-2, "RES, 85.6, 0.1%, 0.125 W, 0805"
R32: library part CMP-0021039-3, "RES, 200, 1%, 0.125 W, AEC-Q200 Grade 0, 0805"
R33 R166: library part CMP-0020284-2, "RES, 6.98 k, 0.1%, 0.125 W, 0805"
R35 R37 R168 R169: library part CMP-0015017-3, "RES, 0, 1%, 0.75 W, AEC-Q200 Grade 0, 1210"
R39 R41 R60 R61 R85 R104 R170 R172 R188 R189 R215 R233: library part CMP-0020842-3, "RES, 10.0 k, 1%, 0.125 W, AEC-Q200 Grade 0, 0805"
R40: library part CMP-0018970-2, "RES, 38.3 k, 0.1%, 0.125 W, 0805"
R44: library part CMP-0018979-2, "RES, 40.2 k, 0.1%, 0.125 W, 0805"
R45: library part CMP-0020412-1, "RES, 965 k, 0.1%, 0.125 W, 0805"
R46 R179: library part CMP-0020733-3, "RES, 47 k, 5%, 0.125 W, AEC-Q200 Grade 0, 0805"
R48: library part CMP-0020200-1, "RES, 597 k, 0.1%, 0.125 W, 0805"
R50: library part CMP-0019441-2, "RES, 100 k, 0.1%, 0.125 W, 0805"
R53: library part CMP-0019568-2, "RES, 14.0 k, 0.1%, 0.125 W, 0805"
R56: library part CMP-0015176-2, "RES, 0.24, 1%, 0.5 W, 1210"
R62 R190: library part CMP-0020645-3, "RES, 1.5 k, 5%, 0.125 W, AEC-Q200 Grade 0, 0805"
R63 R70: library part CMP-0020111-1, "RES, 481 k, 0.1%, 0.125 W, 0805"
R65: library part CMP-0018856-2, "RES, 10.0 k, 0.1%, 0.125 W, 0805"
R66 R69 R71 R72 R191 R193 R197 R199: library part CMP-0023343-1, "RES, 0, 1%, 0.1 W, AEC-Q200 Grade 0, 0603"
R75 R202: library part CMP-0020618-2, "RES, 100, 5%, 0.125 W, 0805"
R76 R78 R83 R88 R90 R93 R96 R100 R203 R207 R210 R211 R217 R221 R223 R230: library part CMP-0020619-2, "RES, 1.0 k, 5%, 0.125 W, 0805"
R77 R204: library part CMP-0020446-2, "RES, 10 k, 5%, 0.125 W, 0805"
R79 R91 R213 R218: library part CMP-0021563-2, "RES, 13.7 k, 1%, 0.125 W, 0805"
R80 R205: library part CMP-0020307-1, "RES, 750, 0.1%, 0.125 W, 0805"
R81 R214: library part CMP-0021575-2, "RES, 15.0 k, 1%, 0.125 W, 0805"
R82 R102 R103 R105 R106 R107 R108 R110 R113 R114 R115 R119 R120 R121 R122 R136 R137 R138 R141 R143 R144 R145 R157 R158 R162 R173 R174 R175 R182 R187 R195 R206 R227 R228 R229 R231 R234 R235 R237 R240 R241 R242 R248 R249 R251 R253 R263 R264 R265: library part CMP-0020833-1, "RES, 0, 1%, 0.5 W, 0805"
R84 R208: library part CMP-0019490-2, "RES, 11.5 k, 0.1%, 0.125 W, 0805"
R86 R216: library part CMP-0021519-2, "RES, 1.00 k, 1%, 0.125 W, 0805"
R87 R146 R154 R163 R167 R176 R183 R186 R196 R209: library part CMP-0021261-3, "RES, 442, 1%, 0.125 W, AEC-Q200 Grade 0, 0805"
R89 R212: library part CMP-0019989-2, "RES, 35.7 k, 0.1%, 0.125 W, 0805"
R92 R219: library part CMP-0019178-1, "RES, 2.00 k, 0.5%, 0.1 W, 0805"
R94 R127 R225 R268: library part CMP-0020845-1, "RES, 10.7 k, 1%, 0.125 W, 0805"
R95 R220: library part CMP-0020620-3, "RES, 10 k, 5%, 0.125 W, AEC-Q200 Grade 0, 0805"
R97 R222: library part CMP-0020234-1, "RES, 626, 0.1%, 0.125 W, 0805"
R98 R226: library part CMP-0020899-2, "RES, 14.7 k, 1%, 0.125 W, 0805"
R101 R232: library part CMP-0021533-1, "RES, 11.0 k, 1%, 0.125 W, 0805"
R109 R236: library part CMP-0018855-2, "RES, 1.00 k, 0.1%, 0.125 W, 0805"
R111 R117 R134 R238 R244 R261: library part CMP-0023143-5, "RES, 49.9, 1%, 0.1 W, 0603"
R112 R135 R239 R262: library part CMP-0018263-2, "RES, 3.90 k, 1%, 0.25 W, 1206"
R116 R139 R243 R266: library part CMP-0018920-2, "RES, 2.20 k, 0.1%, 0.125 W, 0805"
R118 R246: library part CMP-0018978-2, "RES, 4.02 k, 0.1%, 0.125 W, 0805"
R123 R254: library part CMP-0020094-1, "RES, 459, 0.1%, 0.125 W, 0805"
R124 R133 R245 R260: library part CMP-0020700-3, "RES, 300 k, 5%, 0.125 W, AEC-Q200 Grade 0, 0805"
R126 R132 R250 R259: library part CMP-0020698-3, "RES, 3.0 k, 5%, 0.125 W, AEC-Q200 Grade 0, 0805"
R128 R129 R130 R131 R255 R257 R258 R267: library part CMP-0020671-1, "RES, 20 k, 5%, 0.125 W, 0805"
R140: library part CMP-0020142-1, "RES, 4.81 k, 0.1%, 0.125 W, 0805"
R142: library part CMP-0019684-1, "RES, 1.23 k, 0.1%, 0.125 W, 0805"
R151: library part CMP-0018889-1, "RES, 15.4 k, 0.1%, 0.125 W, 0805"
R152: library part CMP-0019607-1, "RES, 16.4 k, 0.1%, 0.125 W, 0805"
R153 R156: library part CMP-0019695-1, "RES, 1.30 k, 0.1%, 0.125 W, 0805"
R159: library part CMP-0020382-2, "RES, 8.16 k, 0.1%, 0.125 W, 0805"
R160: library part CMP-0020373-1, "RES, 887 k, 0.1%, 0.125 W, 0805"
R161: library part CMP-0018949-1, "RES, 301 k, 0.1%, 0.125 W, 0805"
R164: library part CMP-0020071-1, "RES, 42.2 k, 0.1%, 0.125 W, 0805"
R165: library part CMP-0021039-2, "RES, 200, 1%, 0.125 W, 0805"
R171: library part CMP-0019800-1, "RES, 229 k, 0.1%, 0.125 W, 0805"
R177: library part CMP-0019003-1, "RES, 499 k, 0.1%, 0.125 W, 0805"
R178: library part CMP-0020093-2, "RES, 459 k, 0.1%, 0.125 W, 0805"
R180: library part CMP-0020377-1, "RES, 898 k, 0.1%, 0.125 W, 0805"
R181: library part CMP-0020253-1, "RES, 665 k, 0.1%, 0.125 W, 0805"
R184: library part CMP-0020079-1, "RES, 43.2 k, 0.1%, 0.125 W, 0805"
R185: library part CMP-0015406-1, "RES, 0.1, 0.1%, 1 W, 6.35x3.175mm"
R192: library part CMP-0019747-1, "RES, 1.20 M, 0.1%, 0.125 W, 0805"
R198: library part CMP-0020414-1, "RES, 96.5 k, 0.1%, 0.125 W, 0805"
R247 R269: library part CMP-0021752-2, "RES, 5.76 k, 1%, 0.125 W, 0805"
R252 R270: library part CMP-0020278-1, "RES, 6.42 k, 0.1%, 0.125 W, 0805"
RT1 RT2: library part CMP-0002399-3, "Thermistor NTC, 10k ohm, 3%, 0603"
S1 S2: library part CMP-0002133-2, "Switch, Tactile, SPST-NO, 0.05A, 12V, TH"
TP1 TP5 TP8 TP9 TP10 TP12 TP13 TP14 TP17 TP20 TP26 TP28 TP29 TP31 TP32 TP33 TP34 TP35 TP36 TP37 TP40 TP43 TP44 TP45 TP47 TP48 TP49 TP53 TP61 TP63 TP65 TP66 TP67 TP68 TP69 TP70 TP71: library part CMP-0003968-1, "Test Point, SMT"
TP2 TP3 TP6 TP7 TP11 TP15 TP18 TP19 TP21 TP22 TP23 TP24 TP25 TP27 TP38 TP39 TP41 TP42 TP46 TP50 TP52 TP54 TP55 TP56 TP57 TP58 TP59 TP60 TP62: library part CMP-0003825-1, "1mm Test Point, SMT"
TP4 TP16 TP30 TP51 TP64: library part CMP-0055138-1, "Test Point, Miniature, Black, TH"
U1 U2 U3 U17 U18 U21: library part CMP-0089209-1, "Precision, CMOS Input, RRIO, Wide Supply Range Amplifiers"
U4: library part CMP-0067763-2, "LVDS Quad CMOS Differential Line Receiver, NAC0016A (CFP-16)"
U5 U11 U19 U26: library part CMP-0088839-1, "Precision Micropower Shunt Voltage Reference"
U6 U20: library part CMP-0066503-2, "MSP430FR5969 16 MHz Ultra-Low-Power Microcontroller featuring 64 KB FRAM, 2 KB SRAM, 40 IO, RGZ0048B (VQFN-48)"
U7 U22: library part CMP-0081563-2, "Voltage Output, Unidirectional Measurement Current-Shunt Monitor, HKX0008A (CFP-8)"
U8 U23: library part CMP-0077675-3, "Space Grade High-Accuracy Remote and Local Temperature Sensor with Pin-Programmable Bus Address, HKU0010A (CFP-10)"
U9 U24: library part CMP-0068255-1, "Low Power Dual Operational Amplifier, 10-pin CerPACK"
U10 U25: library part CMP-0068426-2, "Low Power Low Offset Voltage Quad Comparator, NAC0014A (CFP-14)"
U12 U27: library part CMP-0069154-1, "12-Bit Micro Power Digital-to-Analog Converter with Rail-to-Rail Output, 10 pin CERPACK"
U13 U15 U16 U28 U30 U31: library part CMP-0067526-3, "Wide Vin Low-Dropout Voltage Regulator, HKU0010A (CFP-10)"
U14 U29: library part CMP-0088499-1, "Precision Micropower Shunt Voltage Reference"
U32 U33: library part CMP-0078485-2, "Radiation Hardened 7-V, 6-A Load Switch, HKR0016A (CFP-16)"
Y1 Y2: library part CMP-0004695-4, "Crystal, 32.768 KHz, 7pF, SMD"
ZZ1: library part CMP-0003616-3
ZZ2: library part CMP-0077236-1
ZZ3: library part CMP-0077237-1
ZZ4: library part CMP-0077238-1

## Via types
v1: diameter 20, hole 10, Top Layer to Bottom Layer, tented both sides, 1161 vias
v2: diameter 19.68, hole 7.87, Top Layer to Bottom Layer, 240 vias

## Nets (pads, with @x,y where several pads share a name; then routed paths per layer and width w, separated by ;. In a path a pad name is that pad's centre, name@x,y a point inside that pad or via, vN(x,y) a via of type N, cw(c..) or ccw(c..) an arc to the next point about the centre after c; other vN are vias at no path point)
"2I2C SCL": R172.1 TP45.1 U20.32 U23.9 | length 1744.2
  Top Layer w8: v1(420.17,2700.25) 546.15,2700.25 548.99,2697.4 TP45.1@556.39,2704.8 ; TP45.1@556.63,2702 597.4,2742.76 U20.32@638.28,2742.76 ; v1(1313.49,3471.68) 1313.62,3471.82 1368.84,3471.82 U23.9@1368.98,3471.96
  Signal w6.5: v1(420.17,2700.25) 438.94,2719.01 438.94,2854.47 1072.86,3488.39 1298.75,3488.39 v1@1314.16,3472.98
  Bottom Layer w8: v1(420.17,2700.25) 555.75,2700.25 R172.1@560,2696 ; R172.1@557.18,2696 R172.1@558.45,2694.73
"2I2C SDA": R170.1 TP44.1 U20.31 U23.8 | length 1673.2
  Top Layer w8: v1(417.61,2773.5) 547.94,2773.5 TP44.1@552.53,2778.09 ; TP44.1@558.45,2774.69 570.76,2762.39 U20.31@636.44,2762.39 ; v1(1313.49,3520.96) 1313.98,3521.46 1368.48,3521.46 U23.8@1368.98,3521.96
  Signal w6.5: v1(417.61,2773.5) 417.61,2860.95 1063.24,3506.59 1298.49,3506.59 v1@1314.16,3522.26
  Bottom Layer w8: v1(417.61,2773.5) 553.5,2773.5 R170.1@556,2776
"2LDO Enable": U20.30 U31.1 | length 3455.4
  Top Layer w8: v1(603.19,2791.19) 612.22,2782.16 U20.30@639.25,2782.16
  Top Layer w12: v1(1581.5,484.23) U31.1@1644.74,484.23
  Signal w10: v1(603.19,2791.19) 603.19,2252.32 916.69,1938.83 916.69,1619.98 1038.36,1498.31 1781.33,1498.31 1828.93,1450.7 1828.93,1046.93 1581.45,799.44 v1@1581.45,484.31
2MISO_4wire: U20.21
2MOSI_3wire: U20.24 U27.9 | length 1143.9
  Top Layer w8: v1@636,2936.79 654.26,2936.79 664.61,2926.44 664.61,2905.41 U20.24@664.84,2905.18 ; v1@1348.77,2560.18 1349.44,2560.85 1412.33,2560.85 U27.9@1413,2561.51
  Bottom Layer w7.5: v1(636,2937.79) 636,2668.85 668.27,2636.57 1269.94,2636.57 v1(1346.73,2559.79)
2MOSI_4wire: U20.20 | length 0
"2Power Sequencing": R255.1 R258.1 U20.28 | length 4309.8
  Top Layer w8: v1(611.2,2905.46) 611.2,2836.92 625.87,2822.25 637.52,2822.25 U20.28@638.08,2821.7
  Signal w10: v1(611.2,2905.46) 640.24,2876.42 640.24,2680.7 776.67,2544.27 776.67,2502.41 889.43,2389.65 915.66,2389.65 1677.18,1628.12 1729.16,1628.12 v1(1729.94,1627.34)
  Bottom Layer w10: R258.1@319.12,506.75 319.12,633.79 367.93,682.6 1465.55,682.6 1676.35,893.39 1676.35,1573.75 v1(1729.94,1627.34) 1730.31,1627.71 R255.1@1802.61,1627.71
"2PWM for Boost": R253.2 TP49.1 U20.29 | length 1337.8
  Top Layer w8: TP49.1@548.69,2859.38 554.03,2854.05 556.62,2856.64 600.08,2813.19 612.3,2813.19 623.61,2801.88 U20.29@638.21,2801.88
  Top Layer w10: v1(474.32,2855.37) 544.13,2855.37 544.34,2855.16 547.22,2858.04 547.28,2857.97 TP49.1@548.69,2859.38 ; R253.2@860.69,1869.34 v1(860.69,1924.15)
  Signal w10: v1(474.32,2855.37) 573.79,2755.9 573.79,2211.05 v1(860.69,1924.15)
"2PWM for Current Source": R202.1 U20.3 | length 3442.2
  Top Layer w8: U20.3@906.97,2703.42 928.44,2703.42 v1(946.04,2685.83) ; v1(3366.87,1354.57) 3366.55,1354.25 3366.55,1309.74 R202.1@3386.33,1289.97
  Signal w10: v1@945.98,2685.91 975.08,2656.8 975.08,2490.4 1745.42,1720.06 2072.09,1720.06 2151.53,1640.62 2151.53,1326.26 2206.5,1271.3 2378.43,1271.3 2461.78,1354.65 v1@3366.81,1354.65
"2Servo Amp": C99.1 R209.2 TP59.1 U20.19 | length 2394.3
  Top Layer w8: v1(743.25,2940.96) 743.25,2940.91 763.27,2920.9 U20.19@763.27,2906.18 ; U20.19@763.27,2905.18 U20.19@763.35,2905.09 ; v1(2094.93,1626.42) 2146.64,1626.42 TP59.1@2146.9,1626.68 2147.16,1626.94 2271.57,1626.94 2272.66,1628.04 2372.32,1628.04 R209.2@2373.79,1629.5
  Signal w10: v1(743.25,2940.96) 743.25,2938.82 896.19,2785.88 896.19,2489.67 1721.77,1664.08 2054.57,1664.08 2092.22,1626.42 v1(2094.93,1626.42)
2SPI_CLK_3wire: U20.11 U27.8 | length 691.8
  Top Layer w8: U20.11@905.57,2860.86 U20.11@905.61,2860.9 ; U20.11@906.97,2860.9 U20.11@905.61,2860.9 ; v1(958.03,2862.72) 956.69,2861.38 906.09,2861.38 U20.11@905.61,2860.9 ; v1@1346.73,2611.66 1347.15,2612.09 1416.66,2612.09 U27.8@1416.96,2611.79
  Bottom Layer w7.5: v1(958.03,2862.72) 1187.11,2862.72 1371.37,2678.46 1371.37,2636.3 v1@1346.73,2611.66
  other v1: 1346.73,2610.6
2SPI_CLK_4wire: U20.40
2SPI_CS1: U20.38
2SPI_CS2: U20.8 U27.7 | length 587.9
  Top Layer w8: U20.8@907.4,2801.41 U20.8@906.97,2801.85 925.31,2801.85 955.17,2831.71 v1(978.25,2831.71) ; v1(1346.73,2661.42) 1347.27,2661.97 1409.49,2661.97 U27.7@1410.65,2663.12
  Bottom Layer w7.5: v1(978.25,2831.71) 1176.44,2831.71 v1(1346.73,2661.42)
2SPI_CS3: U20.35
2TCk: J27.7 U20.15 | length 833.5
  Top Layer w8: J27.7@150,2820.53 J27.7@150.5,2821.03 ; J27.7@150,2821.53 198.1,2869.63 288.91,2869.63 424.17,3004.89 782.48,3004.89 842.01,2945.37 U20.15@842.01,2905.18
2TDI: J27.3 U20.13 | length 859.6
  Top Layer w8: J27.3@150,3020.53 200.71,3071.24 369.81,3071.24 395.48,3045.57 806.59,3045.57 881.38,2970.78 U20.13@881.38,2905.18
2TDO: J27.1 U20.12 | length 958.8
  Top Layer w8: J27.1@150,3121.53 202.59,3174.12 307.34,3174.12 418.4,3063.06 822.66,3063.06 906.97,2978.75 U20.12@906.97,2880.59 U20.12@906.97,2879.58
"2Temp Voltage": R166.1 R168.1 R232.2 RT2.2 TP43.1 U17.10 | length 3971.2
  Top Layer w10: v1(2582.49,589.55) 2647.03,589.55 R232.2@2651.84,594.36
  Top Layer w15: v1(2602.07,3196.8) 2639.68,3159.19 U17.10@2704.48,3159.19 2850.79,3159.19 2959.34,3050.64 2959.34,2836.93 3066,2836.93 3155.93,2747 RT2.2@3255.41,2747 3297.57,2747 3419.98,2869.41 R168.1@3419.98,2895
  Power w15: v1(2582.49,589.55) 2582.49,590.9 2611.09,619.5 2611.09,3187.78 v1(2602.07,3196.8)
  Bottom Layer w8: R166.1@2602,3268 R166.1@2602.07,3267.93 ; v1(2602.07,3196.8) 2602,3196.87 v1@2602.07,3196.93
  Bottom Layer w15: v1@2602.07,3196.93 R166.1@2602.07,3267.93
2TMS: J27.5 U20.14 | length 835.1
  Top Layer w8: J27.5@150,2920.53 J27.5@150.5,2921.03 ; J27.5@150,2921.53 200.35,2971.88 344.17,2971.88 397.23,3024.94 793.54,3024.94 861.69,2956.79 U20.14@861.69,2905.18
5V: J9.2 R65.2 R94.2 TP20.1 | length 3835.5
  Top Layer w15: v1(2573.59,4805.9) R94.2@2655.95,4805.9
  Top Layer w20: v1(2469.7,6336.7) 2469.7,6065.9 2493.33,6042.28 2493.33,6033.94 2612.93,5914.34 2612.93,5505.42 2739.76,5378.59 3544.86,5378.59 J9.2@3739,5184.45 ; R94.2@2655.95,4805.9 R94.2@2656.04,4805.81
  Signal w15: v1(2573.59,4805.9) 2646.05,4733.45 3562.79,4733.45 3653.47,4824.13 3653.47,5106.76 3731.16,5184.45 J9.2@3739,5184.45
  Bottom Layer w8: R65.2@2468.59,6391.83 R65.2@2469.7,6390.72
  Bottom Layer w20: v1(2469.7,6336.7) R65.2@2469.7,6390.72
5V(i): J30.2 R194.2 R225.2 TP55.1 | length 3854.8
  Top Layer w20: v1(2522,2438.5) 2522,2362.94 2466.15,2307.1 TP55.1@2466.15,2108.67 2466.15,2075.06 2653.84,1887.38 2653.84,1553.09 2782.85,1424.08 3535.83,1424.08 J30.2@3735,1224.91 ; v1(2570.2,855.69) 2652.55,855.69 R225.2@2652.65,855.6
  Signal w15: v1(2570.2,855.69) 2633.1,792.79 3543.56,792.79 3639.62,888.85 3639.62,1129.53 J30.2@3735,1224.91
  Bottom Layer w15: R194.2@2464.85,2440.8 2519.7,2440.8 v1(2522,2438.5)
20V: J3.2 R26.2 R91.2 TP5.1 | length 3679.7
  Top Layer w15: R91.2@3495,4434 3495.88,4434.88 v1(3558.73,4434.88)
  Top Layer w20: R26.2@3292.48,7068.45 3299.47,7075.45 TP5.1@3475.45,7075.45 3609.65,7075.45 3652.04,7117.84 3652.04,7257.49 J3.2@3735,7340.45
  Power w20: v1(3558.73,4434.88) 3585.96,4462.1 3585.96,4495.17 3585.96,7191.4 J3.2@3735,7340.45
20V(i): J23.2 R161.2 R218.2 TP40.1 | length 3646.4
  Top Layer w15: R218.2@3495,484 R218.2@3496.01,482.99
  Top Layer w20: R161.2@3289.9,3117.66 3471.66,3117.66 TP40.1@3472,3118 3472,3205.48 3647.62,3381.1 J23.2@3735,3381.1 ; R218.2@3496.01,482.99 v1(3568.34,482.99)
  Power w20: v1(3568.34,482.99) 3568.34,483.79 3592.68,508.13 3592.68,3238.78 J23.2@3735,3381.1
40V: J7.2 R50.2 R79.2 TP13.1 | length 3140
  Top Layer w20: v1(2531.29,6093.84) 2532.37,6093.84 2582.36,6043.86 TP13.1@2598.1,6043.86 ; TP13.1@2616.5,6047.59 2704.39,5959.7 2704.39,5539.57 2814.4,5429.56 3542.69,5429.56 3605.58,5492.45 J7.2@3738,5492.45 3839.23,5391.21 3839.23,4697.76 3792.47,4651 3606,4651 3541,4716 R79.2@3433,4716
  Bottom Layer w20: R50.2@2469.7,6163.63 2469.7,6124.05 2499.91,6093.84 v1(2531.29,6093.84)
40V(i): J28.2 R181.2 R213.2 TP48.1 | length 3101.8
  Top Layer w20: v1(2564,2155.02) TP48.1@2564,2099.1 2579.75,2099.1 2731.55,1947.3 2731.55,1604.73 2850.45,1485.83 3539.48,1485.83 3586.58,1532.93 J28.2@3735,1532.93 3820,1447.93 3820,727.15 3777.86,685.01 3609.1,685.01 3528.11,766 R213.2@3433,766
  Bottom Layer w15: R181.2@2466.15,2212.69 2523.83,2155.02 v1(2564,2155.02)
"Adjustable Current Source": J12.1 Q2.3@2855.63,4931.98 | length 1380.2
  Top Layer w10: Q2.3@2855.63,4931.98 v1(2894.38,4931.98)
  Bottom Layer w15: v1(2894.38,4931.98) 2894.38,4655.71 3116.33,4433.76 3428.96,4433.76 J12.1@3739.14,4123.58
